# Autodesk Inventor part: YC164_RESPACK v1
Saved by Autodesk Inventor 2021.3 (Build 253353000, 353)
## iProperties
Created: 2023-09
Part Number: YC164_RESPACK v1
Material: Generic
Document SubType Name: Modeling
Designer: AdminForWorker
Density: 1 g/cm^3
Appearance: Default
Title: YC164_RESPACK v1
Author: AdminForWorker
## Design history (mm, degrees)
feature "Body1"
body "Solid1"
